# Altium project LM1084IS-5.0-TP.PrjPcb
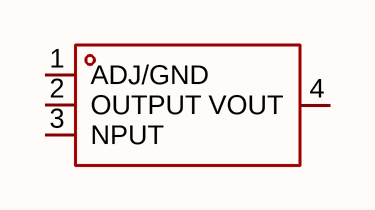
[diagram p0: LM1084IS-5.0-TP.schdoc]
1 sheet, 1 parts. Net scope: global (net labels, ports and power ports of the same name join across sheets).

## Sheet LM1084IS-5.0-TP.schdoc
size 127 x 101 mm

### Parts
U?  lm1084is-5.0-tp  [TO-263-3L_L10.2-W8.7-P2.54-LS15.3-BL-A]  (value not drawn)

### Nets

Not connected (* = marked no-connect by the designer): U? 1(ADJ/GND) 2(OUTPUT) 3(NPUT) 4(VOUT)

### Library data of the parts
U? = lm1084is-5.0-tp: 输出极性:正极;工作电压:12V;输出电压:5V;输出电流:5A;电源纹波抑制比(PSRR):72dB@(120Hz);输出类型:固定;; Manufacturer: TECH PUBLIC(台舟); AddInBom: yes; ModelId: 36f82c99a68444fb91e0c29a020f4027; ModelTransform: 399.999,600.393,0,0,0,0,0,38.386,0; Output Configuration: 正极; Voltage - Supply: 12V; Output Voltage: 5V; Output Current: 5A; Voltage Dropout: 1.5V@(5A); Noise: 0.003%Vout; Output Type: 固定; Number of Outputs: 1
